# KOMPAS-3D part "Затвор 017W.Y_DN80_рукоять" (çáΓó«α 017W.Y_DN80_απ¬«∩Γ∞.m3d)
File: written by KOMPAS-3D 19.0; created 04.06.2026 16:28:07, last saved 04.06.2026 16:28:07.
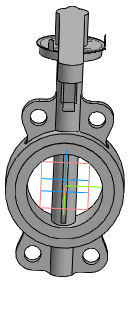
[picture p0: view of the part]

Document properties: Автор: Энергия; Полное имя файла: ..\..\..\3d для проектировщиков\017W разные\x.x Тип 017W.Y(S) Затвор дисковый поворотный межфланцевый\Затвор 017W.Y(S)_DN32-DN350_рукоять\Затвор 017W.Y_DN80_рукоять.a3d

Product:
- Part/product: Затвор 017W.Y_DN80_рукоять
    Масса: 5.21265

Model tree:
1. Операция без истории:1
